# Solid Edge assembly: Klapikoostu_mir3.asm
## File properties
Author: Türk
Template: Iso Assembly.asm
Last saved by: Türk
Revision: 3
Application: Solid Edge
Username: Türk
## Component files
Klapipuks.par
Klapp.par
Klapi vedru_mir.par
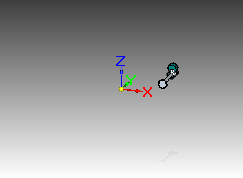
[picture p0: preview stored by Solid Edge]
